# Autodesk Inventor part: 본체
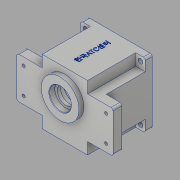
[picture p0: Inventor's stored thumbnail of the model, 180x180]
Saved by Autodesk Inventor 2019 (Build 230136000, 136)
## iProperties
Created: 2020-01
Part Number: 본체
Material: 알루미늄 6061
Document SubType Name: Modeling
Designer: 323-19
Density: 2.7 g/cm^3
Appearance: 알루미늄 - 평지
Mass: 876.469 g
Surface Area: 793.591 cm^2
Volume: 324.618 cm^3
Author: 323-19
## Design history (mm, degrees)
sketch "스케치1"
  geometry: L1 (-47, -47)-(47, -47); L2 (47, -47)-(47, 47); L3 (47, 47)-(-47, 47); L4 (-47, 47)-(-47, -47); L5 (-47, -47)-(47, 47); L6 (47, -47)-(-47, 47); 1 further point
  constraints: 12 end point, 2 midpoint, 2 parallel, 1 horizontal, 1 perpendicular
  dimensions: "d0" = 94 distance of L3.end L2.end; "d1" = 94 distance of L2.end L1.end
extrude "돌출1" new body sketch "스케치1" distance "d2" = 80; taper "d3" = 0 deg
sketch "스케치2"
  geometry: L1 (-70, 30)-(70, 30); L2 (70, 30)-(70, -30); L3 (70, -30)-(-70, -30); L4 (-70, -30)-(-70, 30); L5 (-70, 30)-(70, -30); L6 (70, 30)-(-70, -30); 1 further point
  constraints: 12 end point, 2 midpoint, 2 parallel, 1 horizontal, 1 perpendicular
  dimensions: "d4" = 140 distance of L2.end L3.end; "d5" = 60 distance of L1.end L2.end
extrude "돌출2" join sketch "스케치2" distance "d6" = 13; taper "d7" = 0 deg
sketch "스케치3"
  geometry: C1 r 27.5 at (0, 11); 1 further point
  constraints: 1 centre point, 1 vertical alignment
  dimensions: "d8" = 55 diameter of C1; "d9" = 11 distance of point (0, 0) C1.centre
extrude "돌출3" join sketch "스케치3" distance "d10" = 7; taper "d11" = 0 deg
sketch "스케치4"
  geometry: L1 (70, -30)-(47, -30) reference; L2 (47, -30)-(47, -47) reference; L3 (47, -47)-(-47, -47) reference; L4 (-47, -47)-(-47, -30) reference; L5 (-47, -30)-(-70, -30) reference; L6 (-70, -30)-(-70, 30) reference; L7 (-70, 30)-(-47, 30) reference; L8 (-47, 30)-(-47, 47) reference; L9 (-47, 47)-(47, 47) reference; L10 (47, 47)-(47, 30) reference; L11 (47, 30)-(70, 30) reference; L12 (70, 30)-(70, -30) reference; L13 (47, 30)-(47, 47) reference; L14 (47, 47)-(33, 47); L15 (33, 47)-(33, 30); L16 (33, 30)-(47, 30); L17 (47, 30)-(47, 47); L18 (-47, -47)-(47, -47) reference; L19 (47, -47)-(33, -47); L20 (33, -47)-(33, -30); L21 (33, -30)-(47, -30); L22 (47, -30)-(47, -47); L23 (-47, -47)-(-33, -47); L24 (-33, -47)-(-33, -30); L25 (-33, -30)-(-47, -30); L26 (-47, -30)-(-47, -47); L27 (-47, 47)-(-33, 47); L28 (-33, 47)-(-33, 30); L29 (-33, 30)-(-47, 30); L30 (-47, 30)-(-47, 47); C1 r 27.5 at (0, 11) reference; 1 further point
  constraints: 32 end point, 8 parallel, 4 horizontal, 4 perpendicular
  dimensions: "d12" = 14 distance of L16.end L15.end; "d13" = 17 distance of L15.end L14.end; "d14" = 14 distance of L20.end L21.end; "d15" = 17 distance of L19.end L20.end; "d16" = 14 distance of L25.end L24.end; "d17" = 17 distance of L24.end L23.end; "d18" = 14 distance of L28.end L29.end; "d19" = 17 distance of L27.end L28.end
extrude "돌출4" cut sketch "스케치4" distance "d20" = 70; taper "d21" = 0 deg
sketch "스케치5"
  geometry: C1 r 40 at (0, 0); 1 further point
  constraints: 1 centre point, 1 coincident
  dimensions: "d22" = 80 diameter of C1
extrude "돌출5" cut sketch "스케치5" distance "d23" = 71; taper "d24" = 0 deg
sketch "스케치6"
  geometry: C1 r 43 at (0, 0); 1 further point
  constraints: 1 centre point, 1 coincident
  dimensions: "d25" = 86 diameter of C1
extrude "돌출6" cut sketch "스케치6" distance "d26" = 9; taper "d27" = 0 deg
sketch "스케치7"
  geometry: C1 r 21 at (0, 11); C2 r 15 at (0, -20); 1 further point
  constraints: 2 centre point, 2 vertical alignment
  dimensions: "d28" = 42 diameter of C1; "d29" = 30 diameter of C2; "d30" = 11 distance of point (0, 0) C1.centre; "d31" = 20 distance of point (0, 0) C2.centre
extrude "돌출7" join sketch "스케치7" distance "d32" = 7; taper "d33" = 0 deg
sketch "스케치8"
  geometry: L1 (-47, -30)-(-47, 30) reference; L2 (-47, 30)-(-33, 30) reference; L3 (-33, 30)-(-33, 47) reference; L4 (-33, 47)-(33, 47) reference; L5 (33, 47)-(33, 30) reference; L6 (33, 30)-(47, 30) reference; L7 (47, 30)-(47, -30) reference; L8 (47, -30)-(33, -30) reference; L9 (33, -30)-(33, -47) reference; L10 (33, -47)-(-33, -47) reference; L11 (-33, -47)-(-33, -30) reference; L12 (-33, -30)-(-47, -30) reference; C1 r 40 at (0, 0) reference; C2 r 17.5 at (0, 11); A1 r 21 centre (0, 11) between (8.978, -7.984) and (-8.978, -7.984) reference; A2 r 15 centre (0, -20) between (-8.978, -7.984) and (8.978, -7.984) reference; 1 further point
  constraints: 1 centre point, 1 coincident
  dimensions: "d34" = 35 diameter of C2
extrude "돌출8" cut sketch "스케치8" distance "d35" = 10; taper "d36" = 0 deg
sketch "스케치9"
  geometry: L1 (-47, -30)-(-47, 30) reference; L2 (-47, 30)-(-33, 30) reference; L3 (-33, 30)-(-33, 47) reference; L4 (-33, 47)-(33, 47) reference; L5 (33, 47)-(33, 30) reference; L6 (33, 30)-(47, 30) reference; L7 (47, 30)-(47, -30) reference; L8 (47, -30)-(33, -30) reference; L9 (33, -30)-(33, -47) reference; L10 (33, -47)-(-33, -47) reference; L11 (-33, -47)-(-33, -30) reference; L12 (-33, -30)-(-47, -30) reference; C1 r 17.5 at (0, 11) reference; C2 r 40 at (0, 0) reference; C3 r 11 at (0, -20); A1 r 21 centre (0, 11) between (8.978, -7.984) and (-8.978, -7.984) reference; A2 r 15 centre (0, -20) between (-8.978, -7.984) and (8.978, -7.984) reference; 1 further point
  constraints: 1 centre point, 1 coincident
  dimensions: "d37" = 22 diameter of C3
extrude "돌출9" cut sketch "스케치9" distance "d38" = 7; taper "d39" = 0 deg
sketch "스케치10"
  geometry: L1 (-33, -27)-(-33, -10) reference; L2 (-33, -10)-(-70, -10) reference; L3 (-70, -10)-(-70, 50) reference; L4 (-70, 50)-(-33, 50) reference; L5 (-33, 50)-(-33, 67) reference; L6 (-33, 67)-(33, 67) reference; L7 (33, 67)-(33, 50) reference; L8 (33, 50)-(70, 50) reference; L9 (70, 50)-(70, -10) reference; L10 (70, -10)-(33, -10) reference; L11 (33, -10)-(33, -27) reference; L12 (33, -27)-(-33, -27) reference; C1 r 11 at (0, 0) reference; C2 r 17.5 at (0, 31) reference; C3 r 40 at (0, 20) reference; C4 r 9.5 at (0, 0); A1 r 21 centre (0, 31) between (8.978, 12.016) and (-8.978, 12.016) reference; A2 r 15 centre (0, 0) between (-8.978, 12.016) and (8.978, 12.016) reference; 1 further point
  constraints: 1 centre point, 1 coincident
  dimensions: "d40" = 19 diameter of C4
extrude "돌출10" cut sketch "스케치10" distance "d41" = 3; taper "d42" = 0 deg
sketch "스케치11"
  geometry: C1 r 27.5 at (0, 0) reference; C2 r 16 at (0, 0); 1 further point
  constraints: 1 centre point, 1 coincident
  dimensions: "d43" = 32 diameter of C2
extrude "돌출11" cut sketch "스케치11" distance "d44" = 8.3; taper "d45" = 0 deg
sketch "스케치12"
  geometry: L1 (33, -41)-(33, -58) reference; L2 (33, -58)-(-33, -58) reference; L3 (-33, -58)-(-33, -41) reference; L4 (-33, -41)-(-70, -41) reference; L5 (-70, -41)-(-70, 19) reference; L6 (-70, 19)-(-33, 19) reference; L7 (-33, 19)-(-33, 36) reference; L8 (-33, 36)-(33, 36) reference; L9 (33, 36)-(33, 19) reference; L10 (33, 19)-(70, 19) reference; L11 (70, 19)-(70, -41) reference; L12 (70, -41)-(33, -41) reference; C1 r 16 at (0, 0) reference; C2 r 12.5 at (0, 0); 1 further point
  constraints: 1 centre point, 1 coincident
  dimensions: "d46" = 25 diameter of C2
extrude "돌출12" cut sketch "스케치12" distance "d47" = 4.7; taper "d48" = 0 deg
sketch "스케치13"
  geometry: L1 (47, 47)-(47, -47) reference; L2 (47, -47)-(-47, -47) reference; L3 (-47, -47)-(-47, 47) reference; L4 (-47, 47)-(47, 47) reference; L5 (35.778, 3.994)-(39.8, 3.994); L6 (35.778, -3.994)-(39.8, -3.994); C1 r 43 at (0, 0) reference; C2 r 40 at (0, 0) reference; A1 r 36 centre (0, 0) between (36, 0) and (35.778, 3.994); A2 r 4 centre (36, 0) between (35.778, 3.994) and (35.778, -3.994); A3 r 40 centre (0, 0) between (39.8, 3.994) and (39.8, -3.994) reference; A4 r 40 centre (0, 0) between (39.8, -3.994) and (39.8, 3.994); 1 further point
  constraints: 9 point on circle, 4 end point, 3 centre point, 2 coincident, 1 horizontal, 1 horizontal alignment, 1 parallel
  dimensions: "d49" = 72 diameter of A1; "d50" = 8 diameter of A2
extrude "돌출13" join sketch "스케치13" stored distance "d51" = 4.7; taper "d52" = 0 deg
sketch "스케치14"
  geometry: A1 r 4 centre (-36, 0) between (-35.778, -3.994) and (-35.778, 3.994) reference; A2 r 4 centre (36, 0) between (35.778, 3.994) and (35.778, -3.994) reference; 3 further points
  constraints: 2 coincident
hole "구멍1" sketch "스케치14" at (-36, 0), (36, 0) diameter "d53" = 3.242; stored, may be unused: countersink angle "d57" = 90 deg, drill point angle "d59" = 118 deg; dims "d54" = 7, "d55" = 4, "d56" = 2, "d58" = 9
sketch "스케치16"
  geometry: L1 (47, 47)-(47, -47) reference; L2 (47, -47)-(-47, -47) reference; L3 (-47, -47)-(-47, 47) reference; L4 (-47, 47)-(47, 47) reference; L5 (-40, -40)-(40, -40); L6 (40, -40)-(40, 40); L7 (40, 40)-(-40, 40); L8 (-40, 40)-(-40, -40); L9 (-40, -40)-(40, 40); L10 (40, -40)-(-40, 40); C1 r 43 at (0, 0) reference; 1 further point
  constraints: 12 end point, 2 midpoint, 2 parallel, 1 horizontal, 1 perpendicular
  dimensions: "d60" = 80 distance of L7.end L6.end; "d61" = 80 distance of L6.end L5.end
hole "구멍2" sketch "스케치16" at (40, 40), (-40, 40), (-40, -40), (40, -40) diameter "d62" = 7; stored, may be unused: countersink angle "d66" = 90 deg, drill point angle "d68" = 0 deg; dims "d63" = 7, "d64" = 4, "d65" = 2, "d67" = 10
sketch "스케치17"
  geometry: L1 (35.778, 3.994)-(39.8, 3.994) reference; L2 (-39.8, 3.994)-(-35.778, 3.994) reference; L3 (-35.778, -3.994)-(-39.8, -3.994) reference; L4 (39.8, -3.994)-(35.778, -3.994) reference; L5 (-47, -30)-(-47, 30) reference; L6 (-70, 30)-(-47, 30) reference; L7 (-70, -30)-(-70, 30) reference; L8 (-47, -30)-(-70, -30) reference; L9 (-33, -30)-(-47, -30) reference; L10 (-33, -47)-(-33, -30) reference; L11 (33, -47)-(-33, -47) reference; L12 (33, -30)-(33, -47) reference; L13 (47, -30)-(33, -30) reference; L14 (47, 30)-(47, -30) reference; L15 (47, 30)-(70, 30) reference; L16 (70, 30)-(70, -30) reference; L17 (70, -30)-(47, -30) reference; L18 (-47, 30)-(-33, 30) reference; L19 (-33, 30)-(-33, 47) reference; L20 (-33, 47)-(33, 47) reference; L21 (33, 47)-(33, 30) reference; L22 (33, 30)-(47, 30) reference; L23 (-60, -19)-(60, -19); L24 (60, -19)-(60, 19); L25 (60, 19)-(-60, 19); L26 (-60, 19)-(-60, -19); L27 (-60, -19)-(60, 19); L28 (60, -19)-(-60, 19); C1 r 11 at (0, -20) reference; C2 r 17.5 at (0, 11) reference; A1 r 4 centre (36, 0) between (35.778, 3.994) and (35.778, -3.994) reference; A2 r 40 centre (0, 0) between (39.8, 3.994) and (-39.8, 3.994) reference; A3 r 4 centre (-36, 0) between (-35.778, -3.994) and (-35.778, 3.994) reference; A4 r 40 centre (0, 0) between (-39.8, -3.994) and (39.8, -3.994) reference; A5 r 21 centre (0, 11) between (8.978, -7.984) and (-8.978, -7.984) reference; A6 r 15 centre (0, -20) between (-8.978, -7.984) and (8.978, -7.984) reference; 1 further point
  constraints: 12 end point, 2 midpoint, 2 parallel, 1 horizontal, 1 perpendicular
  dimensions: "d69" = 120 distance of L25.end L24.end; "d70" = 38 distance of L24.end L23.end
hole "구멍3" sketch "스케치17" at (60, 19), (60, -19), (-60, -19), (-60, 19) diameter "d71" = 4.5; stored, may be unused: countersink angle "d75" = 90 deg, drill point angle "d77" = 0 deg; dims "d72" = 7, "d73" = 10, "d74" = 5, "d76" = 13
chamfer "모따기1" distance "d78" = 0.46185; stored, may be unused: second distance "d79" = 2, angle "d80" = 60 deg
chamfer "모따기2" distance "d81" = 1; stored, may be unused: second distance "d82" = 2, angle "d83" = 45 deg
chamfer "모따기3" distance "d84" = 1; stored, may be unused: second distance "d85" = 2, angle "d86" = 45 deg
fillet "모깎기1" dims "d87" = 3
fillet "모깎기2" dims "d88" = 3
fillet "모깎기3" dims "d89" = 3
fillet "모깎기4" dims "d90" = 3
fillet "모깎기5" dims "d91" = 3
node "작업 평면1"
sketch "스케치18"
  geometry: L1 (-11, 80)-(77, 80) reference; 3 further points
  constraints: 1 midpoint, 1 vertical alignment, 1 other
  dimensions: "d93" = 40 distance from line of L1 point (33, 40)
feature "엠보싱1" sketch "스케치18" dims "d0" = 94, "d1" = 94, "d94" = 0.5, "d95" = 0
node "솔리드1"
mirror "미러1"
node "절단 모서리 투영1"
node "절단 모서리 투영2"
node "절단 모서리 투영3"
node "절단 모서리 투영4"
node "절단 모서리 투영5"
node "절단 모서리 투영6"
node "절단 모서리 투영7"
node "절단 모서리 투영10"
node "절단 모서리 투영11"
other parameters: "d92" = 0
